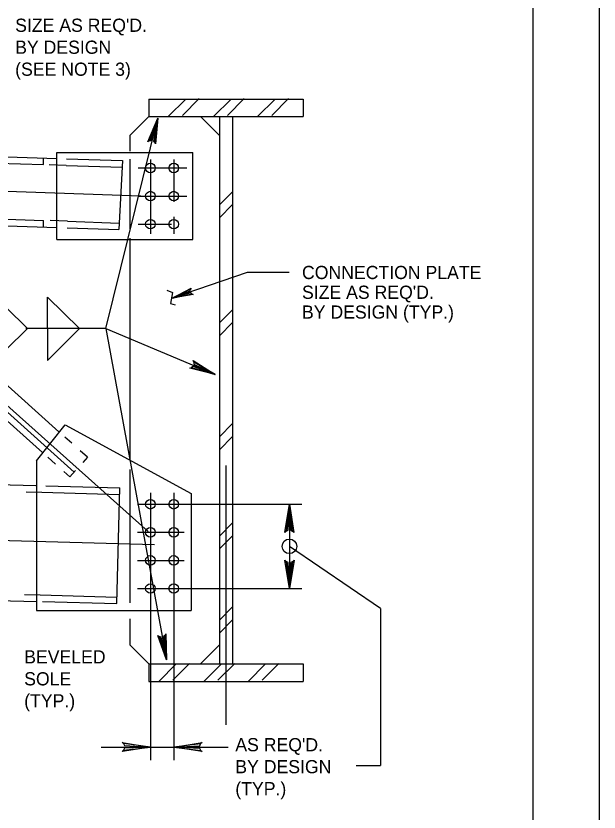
# Model space of a CAD drawing. Extents: x 634656 to 641360, y 298715 to 301183.
# Drawn here: x 638924.9 to 639057.4, y 300129.6 to 300310.7 of the extents above; entities that cross this region are included whole.
import ezdxf

# ---------------------------------------------------------------- set-up
doc = ezdxf.new("R2010")
doc.units = 0
for name, color, linetype in [('1', 7, 'Continuous'), ('2', 7, 'Continuous'), ('PLT-BNDY', 7, 'Continuous')]:
    doc.layers.add(name, color=color, linetype=linetype)

msp = doc.modelspace()

# ---------------------------------------------------------------- linework, layer by layer
at = {"layer": '1'}
for p, q in [((638955.08, 300291.8), (638990.13, 300291.8)), ((638955.08, 300291.8), (638955.08, 300287.8)), ((638959.5, 300287.8), (638963.5, 300291.8)), ((638962.7, 300288.09), (638966.51, 300291.9)), ((638969.77, 300287.8), (638973.77, 300291.8)), ((638972.97, 300288.09), (638976.78, 300291.9)), ((638979.8, 300287.8), (638983.8, 300291.8)), ((638983.01, 300288.09), (638986.82, 300291.9)), ((638990.13, 300291.8), (638990.13, 300287.8)), ((638945.31, 300239.59), (638957.12, 300287.48)), ((638950.75, 300283.48), (638955.08, 300287.8)), ((638955.08, 300287.8), (638990.13, 300287.8)), ((638971.11, 300283.48), (638966.78, 300287.8)), ((638971.11, 300287.8), (638971.11, 300163.28)), ((638974.11, 300287.8), (638974.11, 300163.28)), ((638950.75, 300283.48), (638950.75, 300279.93)), ((638796.34, 300282.96), (638934.15, 300278.28)), ((638800.24, 300281.33), (638931.15, 300276.89)), ((638934.15, 300259.84), (638934.15, 300279.6)), ((638934.15, 300279.6), (638965.09, 300279.6)), ((638965.09, 300259.84), (638965.09, 300279.6)), ((638931.15, 300276.89), (638931.15, 300278.33)), ((638936.32, 300278.21), (638949.07, 300277.78)), ((638949.07, 300277.78), (638948.27, 300262.09)), ((638950.75, 300278.14), (638950.75, 300262.26)), ((638955.43, 300278.02), (638955.43, 300261.14)), ((638960.74, 300278.02), (638960.74, 300268.39)), ((638936.27, 300276.71), (638932.42, 300276.84)), ((638936.27, 300276.71), (638949.02, 300276.28)), ((638952.62, 300276.11), (638963.7, 300276.11)), ((638779.79, 300275.67), (638953.23, 300269.78)), ((638971.11, 300267.71), (638974.11, 300270.71)), ((638952.62, 300269.72), (638963.7, 300269.72)), ((638851.26, 300266.89), (638931.15, 300264.18)), ((638971.11, 300264.78), (638974.11, 300267.78)), ((638851.47, 300265.38), (638934.15, 300262.57)), ((638960.74, 300265.01), (638960.74, 300261.14)), ((638931.15, 300262.62), (638931.15, 300264.18)), ((638936.58, 300263.99), (638932.63, 300264.13)), ((638936.58, 300263.99), (638948.32, 300263.59)), ((638952.62, 300263.33), (638960.26, 300263.33)), ((638954.92, 300193.39), (638877.29, 300262.83)), ((638936.53, 300262.49), (638948.27, 300262.09)), ((638938.12, 300206.94), (638878.96, 300259.86)), ((638934.15, 300259.84), (638965.09, 300259.84)), ((638950.75, 300260.17), (638950.75, 300209.67)), ((638930.89, 300211.4), (638883.9, 300253.43)), ((638977.45, 300252.37), (638960.4, 300246.53)), ((638971.11, 300240.87), (638974.11, 300243.87)), ((638945.31, 300239.59), (638959.07, 300164.2)), ((638945.31, 300239.59), (638970.13, 300229.16)), ((638971.11, 300237.95), (638974.11, 300240.95)), ((638934.62, 300216.11), (638912.94, 300235.5)), ((638971.11, 300214.95), (638974.11, 300217.95)), ((638929.5, 300209.51), (638936.03, 300217.69)), ((638936.03, 300217.69), (638964.69, 300202.08)), ((638937.55, 300213.49), (638935.98, 300214.9)), ((638971.11, 300212.02), (638974.11, 300215.02)), ((638941.12, 300210.3), (638939.45, 300211.79)), ((638929.5, 300209.51), (638929.5, 300175.45)), ((638933.86, 300208.74), (638932.11, 300210.31)), ((638941.12, 300210.3), (638940.04, 300209.09)), ((638800.89, 300207.46), (638929.41, 300203.89)), ((638937.12, 300205.83), (638935.77, 300207.03)), ((638938.42, 300207.28), (638937.12, 300205.83)), ((638950.75, 300207.53), (638950.75, 300177.18)), ((638972.61, 300208.45), (638972.61, 300149.45)), ((638931.66, 300203.83), (638948.5, 300203.36)), ((638947.77, 300176.99), (638948.5, 300203.36)), ((638927.17, 300202.45), (638930.75, 300202.35)), ((638930.75, 300202.35), (638948.46, 300201.86)), ((638955.43, 300202.17), (638955.43, 300141.4)), ((638960.74, 300202.17), (638960.74, 300141.4)), ((638964.69, 300202.08), (638964.69, 300175.45)), ((638952.5, 300199.61), (638989.82, 300199.61)), ((638987.04, 300199.61), (638987.04, 300180.44)), ((638971.11, 300192.36), (638974.11, 300195.36)), ((638952.5, 300193.22), (638963.09, 300193.22)), ((638909.44, 300191.73), (638956.34, 300190.43)), ((638971.11, 300189.44), (638974.11, 300192.44)), ((639007.76, 300175.88), (638987.04, 300190.03)), ((638952.5, 300186.83), (638963.09, 300186.83)), ((638801.05, 300181.06), (638929.58, 300177.49)), ((638952.5, 300180.44), (638989.82, 300180.44)), ((638926.77, 300179.07), (638930.34, 300178.97)), ((638930.34, 300178.97), (638947.81, 300178.49)), ((638930.93, 300177.45), (638947.77, 300176.99)), ((638971.11, 300173.23), (638974.11, 300176.24)), ((638929.5, 300175.45), (638964.69, 300175.45)), ((638950.75, 300173.55), (638950.75, 300167.6)), ((638971.11, 300170.31), (638974.11, 300173.31)), ((638955.08, 300163.28), (638950.75, 300167.6)), ((638971.11, 300167.6), (638966.78, 300163.28)), ((638955.08, 300163.28), (638990.13, 300163.28)), ((638955.08, 300163.28), (638955.08, 300159.28)), ((638957.32, 300159.28), (638961.31, 300163.28)), ((638960.52, 300159.56), (638964.33, 300163.37)), ((638967.59, 300159.28), (638971.59, 300163.28)), ((638970.79, 300159.56), (638974.6, 300163.37)), ((638977.62, 300159.28), (638981.62, 300163.28)), ((638980.82, 300159.56), (638984.63, 300163.37)), ((638990.13, 300163.28), (638990.13, 300159.28)), ((638955.08, 300159.28), (638990.13, 300159.28))]:
    msp.add_line(p, q, dxfattribs=at)
for points in [[(638955.12, 300282.27), (638955.55, 300282.37), (638957.12, 300287.48), (638955.12, 300282.27), (638954.81, 300282.05), (638957.12, 300287.48), (638956.1, 300282.24), (638956.43, 300281.96), (638957.12, 300287.48), (638956.62, 300281.6), (638956.43, 300281.96)], [(638964.88, 300247.46), (638964.61, 300247.72), (638960.4, 300246.53), (638964.88, 300247.46), (638965.16, 300247.35), (638960.4, 300246.53), (638964.46, 300248.15), (638964.51, 300248.51), (638960.4, 300246.53), (638964.67, 300248.8), (638964.51, 300248.51)], [(638959.17, 300248.29), (638960.42, 300247.81), (638960.03, 300245.25), (638961.06, 300244.98)], [(638965.29, 300231.95), (638965.33, 300231.5), (638970.13, 300229.16), (638965.29, 300231.95), (638965.13, 300232.28), (638970.13, 300229.16), (638965.12, 300230.98), (638964.78, 300230.69), (638970.13, 300229.16), (638964.41, 300230.56), (638964.78, 300230.69)], [(638986.27, 300193.48), (638986.72, 300193.71), (638987.04, 300199.61), (638986.27, 300193.48), (638986, 300193.17), (638987.04, 300199.61), (638987.33, 300193.72), (638987.77, 300193.5), (638987.04, 300199.61), (638988.06, 300193.17), (638987.77, 300193.5)], [(638987.81, 300186.57), (638987.37, 300186.34), (638987.04, 300180.44), (638987.81, 300186.57), (638988.08, 300186.88), (638987.04, 300180.44), (638986.75, 300186.33), (638986.31, 300186.55), (638987.04, 300180.44), (638986.02, 300186.88), (638986.31, 300186.55)], [(638958.76, 300169.77), (638958.4, 300169.49), (638959.07, 300164.2), (638958.76, 300169.77), (638958.95, 300170.09), (638959.07, 300164.2), (638957.86, 300169.39), (638957.43, 300169.51), (638959.07, 300164.2), (638957.12, 300169.76), (638957.43, 300169.51)], [(638949.3, 300145.14), (638949.53, 300144.7), (638955.43, 300144.37), (638949.3, 300145.14), (638948.99, 300145.41), (638955.43, 300144.37), (638949.54, 300144.08), (638949.32, 300143.64), (638955.43, 300144.37), (638948.99, 300143.35), (638949.32, 300143.64)], [(638966.87, 300143.6), (638966.64, 300144.05), (638960.74, 300144.37), (638966.87, 300143.6), (638967.19, 300143.33), (638960.74, 300144.37), (638966.64, 300144.66), (638966.85, 300145.1), (638960.74, 300144.37), (638967.19, 300145.4), (638966.85, 300145.1)]]:
    msp.add_lwpolyline(points, dxfattribs=at)
for centre, radius in [((638955.43, 300276.11), 1.09), ((638960.74, 300276.11), 1.09), ((638955.43, 300269.72), 1.09), ((638960.74, 300269.72), 1.09), ((638955.43, 300263.33), 1.09), ((638960.74, 300263.33), 1.09), ((638955.43, 300199.61), 1.09), ((638960.74, 300199.61), 1.09), ((638955.43, 300193.22), 1.09), ((638960.74, 300193.22), 1.09), ((638987.04, 300190.03), 1.65), ((638955.43, 300186.83), 1.09), ((638960.74, 300186.83), 1.09), ((638955.43, 300180.44), 1.09), ((638960.74, 300180.44), 1.09)]:
    msp.add_circle(centre, radius, dxfattribs=at)
at = {"layer": '2'}
for p, q in [((639042.43, 299927.99), (639042.43, 300491.99)), ((638986.96, 300252.37), (638977.45, 300252.37)), ((638945.31, 300239.59), (638927.07, 300239.59)), ((638932.06, 300239.59), (638932.06, 300232.34)), ((638932.06, 300232.34), (638939.31, 300239.59)), ((639007.76, 300175.88), (639007.76, 300140.16)), ((638944.26, 300144.37), (638955.43, 300144.37)), ((638955.43, 300144.37), (638960.74, 300144.37)), ((638960.74, 300144.37), (638973.12, 300144.37)), ((639002.18, 300140.16), (639007.76, 300140.16))]:
    msp.add_line(p, q, dxfattribs=at)
for points in [[(638932.06, 300239.59), (638932.06, 300246.72), (638939.31, 300239.59), (638932.06, 300239.59)], [(638922.6, 300244.34), (638927.47, 300239.59), (638922.6, 300234.84)]]:
    msp.add_lwpolyline(points, dxfattribs=at)
at = {"layer": 'PLT-BNDY'}
msp.add_lwpolyline([(638216.43, 300506.99), (639057.43, 300506.99), (639057.43, 299912.99), (638216.43, 299912.99)], close=True, dxfattribs=at)

# ---------------------------------------------------------------- texts
at = {"layer": '1'}
for s, height, p in [('CONNECTION PLATE', 2.9999, (638989.89, 300250.84)), ("SIZE AS REQ'D.", 2.9999, (638989.89, 300246.34)), ('BY DESIGN (TYP.)', 2.9999, (638989.89, 300241.84)), ('BEVELED', 3, (638926.73, 300163.39)), ('SOLE  ', 3, (638926.73, 300158.39)), ('(TYP.)', 3, (638926.73, 300153.39)), ("AS REQ'D.", 3, (638974.73, 300143.4)), ('BY DESIGN', 3, (638974.73, 300138.4)), ('(TYP.)', 3, (638974.73, 300133.4))]:
    msp.add_text(s, height=height, dxfattribs=at).set_placement(p)
at = {"layer": '2'}
for s, height, p in [("SIZE AS REQ'D.", 2.9999, (638924.68, 300307.09)), ('BY DESIGN', 3, (638924.68, 300302.09)), ('(SEE NOTE 3)', 2.9999, (638924.68, 300297.09))]:
    msp.add_text(s, height=height, dxfattribs=at).set_placement(p)

doc.saveas('drawing.dxf')
